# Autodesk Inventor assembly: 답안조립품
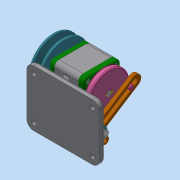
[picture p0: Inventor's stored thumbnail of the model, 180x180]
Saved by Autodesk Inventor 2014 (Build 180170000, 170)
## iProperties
Created: 2020-11
Part Number: 답안조립품
Document SubType Name: Assembly
Designer: net
Author: net
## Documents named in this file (19)
- C:\Users\net\Desktop\601106V1045\답안조립품.iam
- C:\Users\net\Desktop\601106V1045\본체.ipt
- C:\Users\net\Desktop\601106V1045\너트 M8.ipt
- C:\Users\net\Desktop\601106V1045\볼트 M4.ipt
- C:\Users\net\Desktop\601106V1045\와셔 8x15.5.ipt
- C:\Users\net\Desktop\601106V1045\크랭크.ipt
- C:\Users\net\Desktop\601106V1045\핀 3 x 8.ipt
- C:\Users\net\Desktop\601106V1045\힌지 축.ipt
- C:\Users\net\Desktop\601106V1045\힌지.ipt
- C:\Users\net\Desktop\601106V1045\V-벨트풀리.ipt
- C:\Users\net\Desktop\601106V1045\돌림판.ipt
- C:\Users\net\Desktop\601106V1045\베어링 6004.ipt
- C:\Users\net\Desktop\601106V1045\오일 실 17 30 5.ipt
- C:\Users\net\Desktop\601106V1045\축.ipt
- C:\Users\net\Desktop\601106V1045\커버.ipt
- C:\Users\net\Desktop\601106V1045\키 5 x 5 x 12.ipt
- C:\Users\net\Desktop\601106V1045\키 4 x 4 x 8.ipt
- C:\Users\net\Desktop\601106V1045\멈춤나사 M3x5.ipt
- C:\Users\net\Desktop\601106V1045\너트 M10x1.ipt
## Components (3 placed, 2 different names)
1. 핀 3 x 8:1
2. 핀 3 x 8:2
3. V-벨트풀리:1
## Named parameters: d24_d21 = 0, d25_d22 = 0
